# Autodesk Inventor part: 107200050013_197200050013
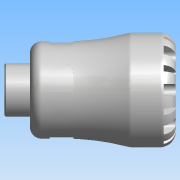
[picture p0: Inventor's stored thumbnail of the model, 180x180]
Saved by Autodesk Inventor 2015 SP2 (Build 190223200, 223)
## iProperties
Created: 2016-12
Part Number: 107200050013_197200050013
Material: PVC-Piping
Description: PLASSON MALE INTEGRAL BRASS THREAD 50X1.1/4" SERIES 1
Document SubType Name: Modeling
Designer: KIM
Mass: 61.7504 g
Surface Area: 140.097 cm^2
Volume: 44.1074 cm^3
Density: 1.4 g/cm^3
Appearance: Smooth - White
Author: KIM
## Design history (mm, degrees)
derived "1072.ipt"
feature "Solid1::1072.ipt"
tag "TaggingFeature1"
body "Solid1"
other parameters: "d0" = 127, "d1" = 34.02, "d3" = 62.5, "d4" = 85, "d6" = 81, "d8" = 72.25, "d13" = 9, "d14" = 9, "d15" = 0, "d17" = 360 deg, "d19" = 8 deg, "d20" = 1, "d21" = 1, "d22" = 8 deg, "d24" = 0, "d26" = 360 deg, "d32" = 8.5, "d33" = 8.5, "d34" = 39.592, "d38" = 19, "d39" = 1.18776, "d42" = 17.5, "d43" = 11.5, "d45" = 17.64, "d46" = 0, "d59" = 360 deg, "d61" = 14.875, "d62" = 1, "d64" = 0, "d65" = 0.85, "d68" = 7.14286, "E_" = 85, "H_" = 127, "l_" = 81, "R_" = 39.592, "l_2" = 19, "d9" = 11.25, "d11" = 85, "d12" = 62.5
